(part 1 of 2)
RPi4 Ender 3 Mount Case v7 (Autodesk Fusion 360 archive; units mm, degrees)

design "RPi4 Ender 3 Mount Case" references "40X40 Extrusion 8 slot v2", "RPi_4_dummy_v2"
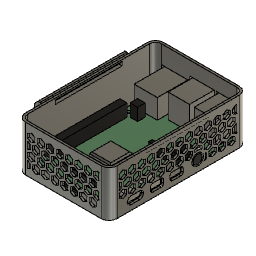
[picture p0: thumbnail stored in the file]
parameter "inner_width" = 60
parameter "inner_length" = 92
parameter "inner_height" = 30
parameter "wall_thickness" = 1.5
parameter "tolerance" = 0.2
parameter "cover_height" = 2
parameter "hole_tolerance" = 1
sketch "Sketch1" plane through (0, 0, 0) normal (0, 0, 1) x axis (1, 0, 0)
  line L1 (60, 0) -> (0, 0)
  line L2 (60, -92) -> (60, 0)
  line L3 (0, -92) -> (60, -92)
  line L4 (0, 0) -> (0, -92)
  point P1 (0, 0)
  point P2 (0, 0)
  point P3 (60, 0)
  point P5 (0, -92)
  horizontal L1
  vertical L2
  horizontal L3
  vertical L4
  coincident P1 P2
  dimension "d6" distance P2 P3 = 60 (= "inner_width")
  dimension "d7" distance P2 P5 = 92 (= "inner_length")
extrude "Extrude1" new body sketch "Sketch1" along normal blind 30 (= "inner_height")
fillet "Fillet1" radius 4
shell "Shell1" outerThickness 1.5 (= "wall_thickness")
sketch "Sketch2" plane through (0, 0, 0) normal (1, 0, 0) x axis (0, 1, 0)
  line L1 (-4, 30) -> (-4, 0)
  line L2 (-88, 30) -> (-4, 30)
  line L3 (-88, 0) -> (-88, 30)
  line L4 (-4, 0) -> (-88, 0)
  line L5 (-23, 28.5) -> (-69, 28.5)
  line L6 (-23, 26.25) -> (-23, 28.5)
  line L7 (-69, 26.25) -> (-23, 26.25)
  line L8 (-69, 28.5) -> (-69, 26.25)
  line L9 (-46, 30) -> (-46, 28.5)
  point P10 (-46, 28.5)
  point P11 (-46, 30)
  point P8 (-23, 26.25)
  point P9 (-69, 26.25)
  point P6 (-69, 28.5)
  horizontal L5
  vertical L6
  horizontal L7
  vertical L8
  midpoint L5 P10
  perpendicular L5 L9
  midpoint L2 P11
  dimension "d32" distance P8 P9 = 46 (= "inner_length / 2")
  dimension "d33" distance P6 P9 = 2.25 (= "wall_thickness * 1.5")
  dimension "d34" distance P10 P11 = 1.5 (= "wall_thickness")
extrude "Extrude2" cut sketch "Sketch2" profile of L5 L6 L7 L8 no distance stored taper -45
work_plane "WorkPlane1"
mirror "Mirror1" mirrorStitchTolerance 0.1
sketch "Sketch1" plane through (0, 0, 30) normal (0, 0, 1) x axis (-1, 0, 0)
  line L1 (-56, 0) -> (-4, 0)
  line L2 (-60, 88) -> (-60, 4)
  line L3 (-4, 92) -> (-56, 92)
  line L4 (0, 4) -> (0, 88)
  line L5 (-61.5, 4) -> (-61.5, 88)
  line L6 (-4, -1.5) -> (-56, -1.5)
  line L7 (1.5, 88) -> (1.5, 4)
  line L8 (-56, 93.5) -> (-4, 93.5)
  arc A1 centre (-4, 4) radius 4 clockwise from (0, 4) to (-4, 0)
  arc A2 centre (-56, 4) radius 4 clockwise from (-56, 0) to (-60, 4)
  arc A3 centre (-56, 88) radius 4 clockwise from (-60, 88) to (-56, 92)
  arc A4 centre (-4, 88) radius 4 clockwise from (-4, 92) to (0, 88)
  arc A5 centre (-56, 88) radius 5.5 clockwise from (-61.5, 88) to (-56, 93.5)
  arc A6 centre (-56, 4) radius 5.5 clockwise from (-56, -1.5) to (-61.5, 4)
  arc A7 centre (-4, 4) radius 5.5 clockwise from (1.5, 4) to (-4, -1.5)
  arc A8 centre (-4, 88) radius 5.5 clockwise from (-4, 93.5) to (1.5, 88)
extrude "Extrude1" new body sketch "Sketch1" along normal blind 2 (= "cover_height")
sketch "Sketch2" plane through (0, 0, 30) normal (0, 0, -1) x axis (1, 0, 0)
  line L1 (4, 93.5) -> (56, 93.5)
  line L2 (-1.5, 4) -> (-1.5, 88)
  line L3 (56, -1.5) -> (4, -1.5)
  line L4 (61.5, 88) -> (61.5, 4)
  line L5 (4, 91.8) -> (56, 91.8)
  line L6 (0.2, 4) -> (0.2, 88)
  line L7 (56, 0.2) -> (4, 0.2)
  line L8 (59.8, 88) -> (59.8, 4)
  arc A1 centre (4, 88) radius 5.5 clockwise from (-1.5, 88) to (4, 93.5)
  arc A2 centre (4, 4) radius 5.5 clockwise from (4, -1.5) to (-1.5, 4)
  arc A3 centre (56, 4) radius 5.5 clockwise from (61.5, 4) to (56, -1.5)
  arc A4 centre (56, 88) radius 5.5 clockwise from (56, 93.5) to (61.5, 88)
  arc A5 centre (4, 88) radius 3.8 clockwise from (0.2, 88) to (4, 91.8)
  arc A6 centre (4, 4) radius 3.8 clockwise from (4, 0.2) to (0.2, 4)
  arc A7 centre (56, 4) radius 3.8 clockwise from (59.8, 4) to (56, 0.2)
  arc A8 centre (56, 88) radius 3.8 clockwise from (56, 91.8) to (59.8, 88)
extrude "Extrude2" add sketch "Sketch2" profile of A8 L8 A7 A6 L6 L7 A5 L5 along normal blind 4.5 (= "wall_thickness * 3")
shell "Shell1" innerThickness 1.5 (= "wall_thickness")
sketch "Sketch3" plane through (0.2, 0, 0) normal (-1, 0, 0) x axis (0, -1, 0)
  line L1 (4, 30) -> (88, 30)
  line L2 (4, 25.5) -> (4, 30)
  line L3 (88, 25.5) -> (4, 25.5)
  line L4 (88, 30) -> (88, 25.5)
  line L5 (69, 26.25) -> (23, 26.25)
  line L6 (69, 28.5) -> (69, 26.25)
  line L7 (23, 26.25) -> (23, 28.5)
  line L8 (23, 28.5) -> (69, 28.5)
extrude "Extrude3" add sketch "Sketch3" profile of L5 L6 L7 L8 along normal blind 1.5 (= "wall_thickness") taper -45
mirror "Mirror1" mirrorStitchTolerance 0.1
offset_faces "OffsetFaces1" distance 0.5
chamfer "Chamfer1" distance 0.5
external_derived "ExternalDerived1" sketch "Sketch3" bodies "Body1", "Body2", "Power USB C", "Micro HDMI 2", "3.5 mm Audio", "Micro HDMI 1", "USB 2.0", "Display"
position "Position1"
sketch "Sketch1" plane through (0, 0, 0) normal (0, 0, 1) x axis (-1, 0, 0)
  line L1 (-60, 4) -> (-60, 88)
  line L2 (-4, 0) -> (-56, 0)
  line L3 (0, 88) -> (0, 4)
  line L4 (-56, 92) -> (-4, 92)
  arc A1 centre (-56, 88) radius 4 clockwise from (-60, 88) to (-56, 92)
  arc A2 centre (-56, 4) radius 4 clockwise from (-56, 0) to (-60, 4)
  arc A3 centre (-4, 4) radius 4 clockwise from (0, 4) to (-4, 0)
  arc A4 centre (-4, 88) radius 4 clockwise from (-4, 92) to (0, 88)
  circle C1 centre (-55.5, 24.9993) radius 1.35
  circle C2 centre (-6.5, 24.9993) radius 1.35
  circle C3 centre (-6.5, 82.9993) radius 1.35
  circle C4 centre (-55.5, 82.9993) radius 1.35
extrude "Extrude3" add sketch "Sketch1" profile of C1 C2 C3 C4 to an object
offset_faces "OffsetFaces1" distance 1.2
sketch "Sketch2" plane through (0, 1.5, 0) normal (0, 1, 0) x axis (-1, 0, 0)
  line L1 (-4, 30) -> (-4, -1.5)
  line L2 (-56, 30) -> (-4, 30)
  line L3 (-56, -1.5) -> (-56, 30)
  line L4 (-4, -1.5) -> (-56, -1.5)
  line L5 (-42.65, 3) -> (-57.35, 3)
  line L6 (-42.65, 19.5) -> (-42.65, 3)
  line L7 (-57.35, 19.5) -> (-42.65, 19.5)
  line L8 (-57.35, 3) -> (-57.35, 19.5)
  line L9 (-24.65, 3) -> (-39.35, 3)
  line L10 (-24.65, 19.5) -> (-24.65, 3)
  line L11 (-39.35, 19.5) -> (-24.65, 19.5)
  line L12 (-39.35, 3) -> (-39.35, 19.5)
  line L13 (-5.25, 3) -> (-21.25, 3)
  line L14 (-5.25, 16.5) -> (-5.25, 3)
  line L15 (-21.25, 16.5) -> (-5.25, 16.5)
  line L16 (-21.25, 3) -> (-21.25, 16.5)
  line L17 (-41.65, 2) -> (-58.35, 2)
  line L18 (-41.65, 20.5) -> (-41.65, 2)
  line L19 (-58.35, 20.5) -> (-41.65, 20.5)
  line L20 (-58.35, 2) -> (-58.35, 20.5)
  line L21 (-23.65, 2) -> (-40.35, 2)
  line L22 (-23.65, 20.5) -> (-23.65, 2)
  line L23 (-40.35, 20.5) -> (-23.65, 20.5)
  line L24 (-40.35, 2) -> (-40.35, 20.5)
  line L25 (-4.25, 2) -> (-22.25, 2)
  line L26 (-4.25, 17.5) -> (-4.25, 2)
  line L27 (-22.25, 17.5) -> (-4.25, 17.5)
  line L28 (-22.25, 2) -> (-22.25, 17.5)
  dimension "d44" = 1 (= "hole_tolerance")
  dimension "d45" = 1 (= "d44")
  dimension "d46" = 1 (= "d45")
extrude "Extrude5" cut sketch "Sketch2" profile of L1 L3 L19 L20 L18 L17 L23 L22 L24 L21 L28 L27 L26 L25 against normal blind 3 (magnitude of "-wall_thickness * 2")
sketch "Sketch3" plane through (61.5, 0, 0) normal (1, 0, 0) x axis (0, 1, 0)
  line L1 (-88, -1.5) -> (-88, 30)
  line L2 (-4, -1.5) -> (-88, -1.5)
  line L3 (-4, 30) -> (-4, -1.5)
  line L4 (-88, 30) -> (-4, 30)
  line L5 (-70.7993, 4.7) -> (-70.7993, 4.5)
  line L6 (-78.2993, 6.2) -> (-72.2993, 6.2)
  line L7 (-79.7993, 4.5) -> (-79.7993, 4.7)
  line L8 (-72.2993, 3) -> (-78.2993, 3)
  line L9 (-56.9493, 5.8) -> (-56.9493, 3.5)
  line L10 (-63.5493, 6.3) -> (-57.4493, 6.3)
  line L11 (-64.0493, 3.5) -> (-64.0493, 5.8)
  line L12 (-57.4493, 3) -> (-63.5493, 3)
  line L13 (-43.4493, 5.8) -> (-43.4493, 3.5)
  line L14 (-50.0493, 6.3) -> (-43.9493, 6.3)
  line L15 (-50.5493, 3.5) -> (-50.5493, 5.8)
  line L16 (-43.9493, 3) -> (-50.0493, 3)
  line L17 (-80.7993, 4.5) -> (-80.7993, 4.7)
  line L18 (-72.2993, 2) -> (-78.2993, 2)
  line L19 (-69.7993, 4.7) -> (-69.7993, 4.5)
  line L20 (-78.2993, 7.2) -> (-72.2993, 7.2)
  line L21 (-65.0493, 3.5) -> (-65.0493, 5.8)
  line L22 (-57.4493, 2) -> (-63.5493, 2)
  line L23 (-55.9493, 5.8) -> (-55.9493, 3.5)
  line L24 (-63.5493, 7.3) -> (-57.4493, 7.3)
  line L25 (-51.5493, 3.5) -> (-51.5493, 5.8)
  line L26 (-43.9493, 2) -> (-50.0493, 2)
  line L27 (-42.4493, 5.8) -> (-42.4493, 3.5)
  line L28 (-50.0493, 7.3) -> (-43.9493, 7.3)
  arc A1 centre (-72.2993, 4.5) radius 1.5 clockwise from (-70.7993, 4.5) to (-72.2993, 3)
  arc A2 centre (-72.2993, 4.7) radius 1.5 clockwise from (-72.2993, 6.2) to (-70.7993, 4.7)
  arc A3 centre (-78.2993, 4.7) radius 1.5 clockwise from (-79.7993, 4.7) to (-78.2993, 6.2)
  arc A4 centre (-78.2993, 4.5) radius 1.5 clockwise from (-78.2993, 3) to (-79.7993, 4.5)
  arc A5 centre (-57.4493, 3.5) radius 0.5 clockwise from (-56.9493, 3.5) to (-57.4493, 3)
  arc A6 centre (-57.4493, 5.8) radius 0.5 clockwise from (-57.4493, 6.3) to (-56.9493, 5.8)
  arc A7 centre (-63.5493, 5.8) radius 0.5 clockwise from (-64.0493, 5.8) to (-63.5493, 6.3)
  arc A8 centre (-63.5493, 3.5) radius 0.5 clockwise from (-63.5493, 3) to (-64.0493, 3.5)
  arc A9 centre (-43.9493, 3.5) radius 0.5 clockwise from (-43.4493, 3.5) to (-43.9493, 3)
  arc A10 centre (-43.9493, 5.8) radius 0.5 clockwise from (-43.9493, 6.3) to (-43.4493, 5.8)
  arc A11 centre (-50.0493, 5.8) radius 0.5 clockwise from (-50.5493, 5.8) to (-50.0493, 6.3)
  arc A12 centre (-50.0493, 3.5) radius 0.5 clockwise from (-50.0493, 3) to (-50.5493, 3.5)
  circle C1 centre (-32.4993, 6) radius 3
  arc A13 centre (-78.2993, 4.5) radius 2.5 clockwise from (-78.2993, 2) to (-80.7993, 4.5)
  arc A14 centre (-72.2993, 4.5) radius 2.5 clockwise from (-69.7993, 4.5) to (-72.2993, 2)
  arc A15 centre (-72.2993, 4.7) radius 2.5 clockwise from (-72.2993, 7.2) to (-69.7993, 4.7)
  arc A16 centre (-78.2993, 4.7) radius 2.5 clockwise from (-80.7993, 4.7) to (-78.2993, 7.2)
  arc A17 centre (-63.5493, 3.5) radius 1.5 clockwise from (-63.5493, 2) to (-65.0493, 3.5)
  arc A18 centre (-57.4493, 3.5) radius 1.5 clockwise from (-55.9493, 3.5) to (-57.4493, 2)
  arc A19 centre (-57.4493, 5.8) radius 1.5 clockwise from (-57.4493, 7.3) to (-55.9493, 5.8)
  arc A20 centre (-63.5493, 5.8) radius 1.5 clockwise from (-65.0493, 5.8) to (-63.5493, 7.3)
  arc A21 centre (-50.0493, 3.5) radius 1.5 clockwise from (-50.0493, 2) to (-51.5493, 3.5)
  arc A22 centre (-43.9493, 3.5) radius 1.5 clockwise from (-42.4493, 3.5) to (-43.9493, 2)
  arc A23 centre (-43.9493, 5.8) radius 1.5 clockwise from (-43.9493, 7.3) to (-42.4493, 5.8)
  arc A24 centre (-50.0493, 5.8) radius 1.5 clockwise from (-51.5493, 5.8) to (-50.0493, 7.3)
  circle C2 centre (-32.4993, 6) radius 4
  dimension "d49" = 1 (= "hole_tolerance")
  dimension "d50" = 1 (= "hole_tolerance")
  dimension "d51" = 1 (= "hole_tolerance")
  dimension "d52" = 1 (= "hole_tolerance")
extrude "Extrude6" cut sketch "Sketch3" profile of A16 L20 A15 L19 L18 A14 A13 L17 L24 A20 A19 L23 L22 A18 A17 L21 L28 A23 A24 L27 L26 A22 A21 L25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 against normal blind 3 (magnitude of "-wall_thickness * 2")
sketch "Sketch5" plane through (61.5, 0, 0) normal (1, 0, 0) x axis (0, 1, 0)
  line L1 (-65.0493, 5.8) -> (-65.0493, 3.5)
  line L2 (-57.4493, 7.3) -> (-63.5493, 7.3)
  line L3 (-55.9493, 3.5) -> (-55.9493, 5.8)
  line L4 (-63.5493, 2) -> (-57.4493, 2)
  line L5 (-51.5493, 5.8) -> (-51.5493, 3.5)
  line L6 (-43.9493, 7.3) -> (-50.0493, 7.3)
  line L7 (-42.4493, 3.5) -> (-42.4493, 5.8)
  line L8 (-50.0493, 2) -> (-43.9493, 2)
  line L9 (-80.7993, 4.7) -> (-80.7993, 4.5)
  line L10 (-72.2993, 7.2) -> (-78.2993, 7.2)
  line L11 (-69.7993, 4.5) -> (-69.7993, 4.7)
  line L12 (-78.2993, 2) -> (-72.2993, 2)
  line L13 (-88, -1.5) -> (-88, 30)
  line L14 (-4, -1.5) -> (-88, -1.5)
  line L15 (-4, 30) -> (-4, -1.5)
  line L16 (-88, 30) -> (-4, 30)
  line L17 (-5.5, 0) -> (-86.5, 0)
  line L18 (-5.5, 28.5) -> (-5.5, 0)
  line L19 (-86.5, 28.5) -> (-5.5, 28.5)
  line L20 (-86.5, 0) -> (-86.5, 28.5)
  line L21 (-72.2993, 8.7) -> (-78.2993, 8.7)
  line L22 (-68.2993, 4.5) -> (-68.2993, 4.7)
  line L23 (-78.2993, 0.5) -> (-72.2993, 0.5)
  line L24 (-82.2993, 4.7) -> (-82.2993, 4.5)
  line L25 (-54.4493, 3.5) -> (-54.4493, 5.8)
  line L26 (-57.4493, 8.8) -> (-63.5493, 8.8)
  line L27 (-66.5493, 5.8) -> (-66.5493, 3.5)
  line L28 (-63.5493, 0.5) -> (-57.4493, 0.5)
  line L29 (-40.9493, 3.5) -> (-40.9493, 5.8)
  line L30 (-43.9493, 8.8) -> (-50.0493, 8.8)
  line L31 (-53.0493, 5.8) -> (-53.0493, 3.5)
  line L32 (-50.0493, 0.5) -> (-43.9493, 0.5)
  line L33 (-87.25, 19.6699) -> (-84.75, 18.2265)
  line L34 (-89.75, 18.2265) -> (-87.25, 19.6699)
  line L35 (-89.75, 15.3397) -> (-89.75, 18.2265)
  line L36 (-87.25, 13.8964) -> (-89.75, 15.3397)
  line L37 (-84.75, 15.3397) -> (-87.25, 13.8964)
  line L38 (-84.75, 18.2265) -> (-84.75, 15.3397)
  line L39 (-84, 25.5) -> (-81.5, 24.0566)
  line L40 (-86.5, 24.0566) -> (-84, 25.5)
  line L41 (-86.5, 21.1699) -> (-86.5, 24.0566)
  line L42 (-84, 19.7265) -> (-86.5, 21.1699)
  line L43 (-81.5, 21.1699) -> (-84, 19.7265)
  line L44 (-81.5, 24.0566) -> (-81.5, 21.1699)
  line L45 (-77.5, 25.5) -> (-75, 24.0566)
  line L46 (-80, 24.0566) -> (-77.5, 25.5)
  line L47 (-80, 21.1699) -> (-80, 24.0566)
  line L48 (-77.5, 19.7265) -> (-80, 21.1699)
  line L49 (-75, 21.1699) -> (-77.5, 19.7265)
  line L50 (-75, 24.0566) -> (-75, 21.1699)
  line L51 (-80.75, 19.6699) -> (-78.25, 18.2265)
  line L52 (-83.25, 18.2265) -> (-80.75, 19.6699)
  line L53 (-83.25, 15.3397) -> (-83.25, 18.2265)
  line L54 (-80.75, 13.8964) -> (-83.25, 15.3397)
  line L55 (-78.25, 18.2265) -> (-78.25, 15.3397)
  line L56 (-78.25, 15.3397) -> (-80.75, 13.8964)
  line L57 (-71, 25.5) -> (-68.5, 24.0566)
  line L58 (-73.5, 24.0566) -> (-71, 25.5)
  line L59 (-73.5, 21.1699) -> (-73.5, 24.0566)
  line L60 (-71, 19.7265) -> (-73.5, 21.1699)
  line L61 (-68.5, 21.1699) -> (-71, 19.7265)
  line L62 (-68.5, 24.0566) -> (-68.5, 21.1699)
  line L63 (-74.25, 19.6699) -> (-71.75, 18.2265)
  line L64 (-76.75, 18.2265) -> (-74.25, 19.6699)
  line L65 (-76.75, 15.3397) -> (-76.75, 18.2265)
  line L66 (-74.25, 13.8964) -> (-76.75, 15.3397)
  line L67 (-71.75, 18.2265) -> (-71.75, 15.3397)
  line L68 (-71.75, 15.3397) -> (-74.25, 13.8964)
  line L69 (-64.5, 25.5) -> (-62, 24.0566)
  line L70 (-67, 24.0566) -> (-64.5, 25.5)
  line L71 (-67, 21.1699) -> (-67, 24.0566)
  line L72 (-64.5, 19.7265) -> (-67, 21.1699)
  line L73 (-62, 21.1699) -> (-64.5, 19.7265)
  line L74 (-62, 24.0566) -> (-62, 21.1699)
  line L75 (-67.75, 19.6699) -> (-65.25, 18.2265)
  line L76 (-70.25, 18.2265) -> (-67.75, 19.6699)
  line L77 (-70.25, 15.3397) -> (-70.25, 18.2265)
  line L78 (-67.75, 13.8964) -> (-70.25, 15.3397)
  line L79 (-65.25, 18.2265) -> (-65.25, 15.3397)
  line L80 (-65.25, 15.3397) -> (-67.75, 13.8964)
  line L81 (-58, 25.5) -> (-55.5, 24.0566)
  line L82 (-60.5, 24.0566) -> (-58, 25.5)
  line L83 (-60.5, 21.1699) -> (-60.5, 24.0566)
  line L84 (-58, 19.7265) -> (-60.5, 21.1699)
  line L85 (-55.5, 21.1699) -> (-58, 19.7265)
  line L86 (-55.5, 24.0566) -> (-55.5, 21.1699)
  line L87 (-61.25, 19.6699) -> (-58.75, 18.2265)
  line L88 (-63.75, 18.2265) -> (-61.25, 19.6699)
  line L89 (-63.75, 15.3397) -> (-63.75, 18.2265)
  line L90 (-61.25, 13.8964) -> (-63.75, 15.3397)
  line L91 (-58.75, 18.2265) -> (-58.75, 15.3397)
  line L92 (-58.75, 15.3397) -> (-61.25, 13.8964)
  line L93 (-51.5, 25.5) -> (-49, 24.0566)
  line L94 (-54, 24.0566) -> (-51.5, 25.5)
  line L95 (-54, 21.1699) -> (-54, 24.0566)
  line L96 (-51.5, 19.7265) -> (-54, 21.1699)
  line L97 (-49, 21.1699) -> (-51.5, 19.7265)
  line L98 (-49, 24.0566) -> (-49, 21.1699)
  line L99 (-54.75, 19.6699) -> (-52.25, 18.2265)
  line L100 (-57.25, 18.2265) -> (-54.75, 19.6699)
  line L101 (-57.25, 15.3397) -> (-57.25, 18.2265)
  line L102 (-54.75, 13.8964) -> (-57.25, 15.3397)
  line L103 (-52.25, 18.2265) -> (-52.25, 15.3397)
  line L104 (-52.25, 15.3397) -> (-54.75, 13.8964)
  line L105 (-45, 25.5) -> (-42.5, 24.0566)
  line L106 (-47.5, 24.0566) -> (-45, 25.5)
  line L107 (-47.5, 21.1699) -> (-47.5, 24.0566)
  line L108 (-45, 19.7265) -> (-47.5, 21.1699)
  line L109 (-42.5, 21.1699) -> (-45, 19.7265)
  line L110 (-42.5, 24.0566) -> (-42.5, 21.1699)
  line L111 (-48.25, 19.6699) -> (-45.75, 18.2265)
  line L112 (-50.75, 18.2265) -> (-48.25, 19.6699)
  line L113 (-50.75, 15.3397) -> (-50.75, 18.2265)
  line L114 (-48.25, 13.8964) -> (-50.75, 15.3397)
  line L115 (-45.75, 18.2265) -> (-45.75, 15.3397)
  line L116 (-45.75, 15.3397) -> (-48.25, 13.8964)
  line L117 (-38.5, 25.5) -> (-36, 24.0566)
  line L118 (-41, 24.0566) -> (-38.5, 25.5)
  line L119 (-41, 21.1699) -> (-41, 24.0566)
  line L120 (-38.5, 19.7265) -> (-41, 21.1699)
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  point P90 (-87.25, 16.7831)
  point P97 (-84, 22.6132)
  point P85 (-87.25, 19.6699)
  point P94 (-86.5, 21.1699)
  point P92 (-84, 25.5)
  vertical L38
  vertical L44
  collinear L20 L41
  dimension "d81" = 1.5 (= "wall_thickness")
  dimension "d84" = 1.5 (= "wall_thickness")
  dimension "d85" distance P90 L38 = 2.5
  dimension "d86" distance P97 L44 = 2.5
  dimension "d87" distance P85 P94 = 1.5 (= "wall_thickness")
  dimension "d88" distance L20 P85 = 0.75 (= "wall_thickness / 2")
  dimension "d95" distance L19 P92 = 3
  dimension "d91" R-Pattern1-uDistance = 6.5
  dimension "d92" R-Pattern1-vDistance = -11.5
extrude "Extrude9" cut sketch "Sketch5" no distance stored
sketch "Sketch6" plane through (0, -93.5, 0) normal (0, -1, 0) x axis (1, 0, 0)
  line L1 (56, 30) -> (56, -1.5)
  line L2 (4, 30) -> (56, 30)
  line L3 (4, -1.5) -> (4, 30)
  line L4 (56, -1.5) -> (4, -1.5)
  line L5 (54.5, 0) -> (5.5, 0)
  line L6 (54.5, 28.5) -> (54.5, 0)
  line L7 (5.5, 28.5) -> (54.5, 28.5)
  line L8 (5.5, 0) -> (5.5, 28.5)
  line L9 (8, 25.5) -> (10.5, 24.0566)
  line L10 (5.5, 24.0566) -> (8, 25.5)
  line L11 (5.5, 21.1699) -> (5.5, 24.0566)
  line L12 (8, 19.7265) -> (5.5, 21.1699)
  line L13 (10.5, 21.1699) -> (8, 19.7265)
  line L14 (10.5, 24.0566) -> (10.5, 21.1699)
  line L15 (4.75, 19.6699) -> (7.25, 18.2265)
  line L16 (2.25, 18.2265) -> (4.75, 19.6699)
  line L17 (2.25, 15.3397) -> (2.25, 18.2265)
  line L18 (4.75, 13.8964) -> (2.25, 15.3397)
  line L19 (7.25, 15.3397) -> (4.75, 13.8964)
  line L20 (7.25, 18.2265) -> (7.25, 15.3397)
  line L21 (14.5, 25.5) -> (17, 24.0566)
  line L22 (12, 24.0566) -> (14.5, 25.5)
  line L23 (12, 21.1699) -> (12, 24.0566)
  line L24 (14.5, 19.7265) -> (12, 21.1699)
  line L25 (17, 21.1699) -> (14.5, 19.7265)
  line L26 (17, 24.0566) -> (17, 21.1699)
  line L27 (11.25, 19.6699) -> (13.75, 18.2265)
  line L28 (8.75, 18.2265) -> (11.25, 19.6699)
  line L29 (8.75, 15.3397) -> (8.75, 18.2265)
  line L30 (11.25, 13.8964) -> (8.75, 15.3397)
  line L31 (13.75, 18.2265) -> (13.75, 15.3397)
  line L32 (13.75, 15.3397) -> (11.25, 13.8964)
  line L33 (21, 25.5) -> (23.5, 24.0566)
  line L34 (18.5, 24.0566) -> (21, 25.5)
  line L35 (18.5, 21.1699) -> (18.5, 24.0566)
  line L36 (21, 19.7265) -> (18.5, 21.1699)
  line L37 (23.5, 21.1699) -> (21, 19.7265)
  line L38 (23.5, 24.0566) -> (23.5, 21.1699)
  line L39 (17.75, 19.6699) -> (20.25, 18.2265)
  line L40 (15.25, 18.2265) -> (17.75, 19.6699)
  line L41 (15.25, 15.3397) -> (15.25, 18.2265)
  line L42 (17.75, 13.8964) -> (15.25, 15.3397)
  line L43 (20.25, 18.2265) -> (20.25, 15.3397)
  line L44 (20.25, 15.3397) -> (17.75, 13.8964)
  line L45 (27.5, 25.5) -> (30, 24.0566)
  line L46 (25, 24.0566) -> (27.5, 25.5)
  line L47 (25, 21.1699) -> (25, 24.0566)
  line L48 (27.5, 19.7265) -> (25, 21.1699)
  line L49 (30, 21.1699) -> (27.5, 19.7265)
  line L50 (30, 24.0566) -> (30, 21.1699)
  line L51 (24.25, 19.6699) -> (26.75, 18.2265)
  line L52 (21.75, 18.2265) -> (24.25, 19.6699)
  line L53 (21.75, 15.3397) -> (21.75, 18.2265)
  line L54 (24.25, 13.8964) -> (21.75, 15.3397)
  line L55 (26.75, 18.2265) -> (26.75, 15.3397)
  line L56 (26.75, 15.3397) -> (24.25, 13.8964)
  line L57 (34, 25.5) -> (36.5, 24.0566)
  line L58 (31.5, 24.0566) -> (34, 25.5)
  line L59 (31.5, 21.1699) -> (31.5, 24.0566)
  line L60 (34, 19.7265) -> (31.5, 21.1699)
  line L61 (36.5, 21.1699) -> (34, 19.7265)
  line L62 (36.5, 24.0566) -> (36.5, 21.1699)
  line L63 (30.75, 19.6699) -> (33.25, 18.2265)
  line L64 (28.25, 18.2265) -> (30.75, 19.6699)
  line L65 (28.25, 15.3397) -> (28.25, 18.2265)
  line L66 (30.75, 13.8964) -> (28.25, 15.3397)
  line L67 (33.25, 18.2265) -> (33.25, 15.3397)
  line L68 (33.25, 15.3397) -> (30.75, 13.8964)
  line L69 (40.5, 25.5) -> (43, 24.0566)
  line L70 (38, 24.0566) -> (40.5, 25.5)
  line L71 (38, 21.1699) -> (38, 24.0566)
  line L72 (40.5, 19.7265) -> (38, 21.1699)
  line L73 (43, 21.1699) -> (40.5, 19.7265)
  line L74 (43, 24.0566) -> (43, 21.1699)
  line L75 (37.25, 19.6699) -> (39.75, 18.2265)
  line L76 (34.75, 18.2265) -> (37.25, 19.6699)
  line L77 (34.75, 15.3397) -> (34.75, 18.2265)
  line L78 (37.25, 13.8964) -> (34.75, 15.3397)
  line L79 (39.75, 18.2265) -> (39.75, 15.3397)
  line L80 (39.75, 15.3397) -> (37.25, 13.8964)
  line L81 (47, 25.5) -> (49.5, 24.0566)
  line L82 (44.5, 24.0566) -> (47, 25.5)
  line L83 (44.5, 21.1699) -> (44.5, 24.0566)
  line L84 (47, 19.7265) -> (44.5, 21.1699)
  line L85 (49.5, 21.1699) -> (47, 19.7265)
  line L86 (49.5, 24.0566) -> (49.5, 21.1699)
  line L87 (43.75, 19.6699) -> (46.25, 18.2265)
  line L88 (41.25, 18.2265) -> (43.75, 19.6699)
  line L89 (41.25, 15.3397) -> (41.25, 18.2265)
  line L90 (43.75, 13.8964) -> (41.25, 15.3397)
  line L91 (46.25, 18.2265) -> (46.25, 15.3397)
  line L92 (46.25, 15.3397) -> (43.75, 13.8964)
  line L93 (53.5, 25.5) -> (56, 24.0566)
  line L94 (51, 24.0566) -> (53.5, 25.5)
  line L95 (51, 21.1699) -> (51, 24.0566)
  line L96 (53.5, 19.7265) -> (51, 21.1699)
  line L97 (56, 21.1699) -> (53.5, 19.7265)
  line L98 (56, 24.0566) -> (56, 21.1699)
  line L99 (50.25, 19.6699) -> (52.75, 18.2265)
  line L100 (47.75, 18.2265) -> (50.25, 19.6699)
  line L101 (47.75, 15.3397) -> (47.75, 18.2265)
  line L102 (50.25, 13.8964) -> (47.75, 15.3397)
  line L103 (52.75, 18.2265) -> (52.75, 15.3397)
  line L104 (52.75, 15.3397) -> (50.25, 13.8964)
  line L105 (8, 14) -> (10.5, 12.5566)
  line L106 (5.5, 12.5566) -> (8, 14)
  line L107 (5.5, 9.6699) -> (5.5, 12.5566)
  line L108 (8, 8.2265) -> (5.5, 9.6699)
  line L109 (10.5, 9.6699) -> (8, 8.2265)
  line L110 (10.5, 12.5566) -> (10.5, 9.6699)
  line L111 (4.75, 8.1699) -> (7.25, 6.7265)
  line L112 (2.25, 6.7265) -> (4.75, 8.1699)
  line L113 (2.25, 3.8397) -> (2.25, 6.7265)
  line L114 (4.75, 2.3964) -> (2.25, 3.8397)
  line L115 (7.25, 6.7265) -> (7.25, 3.8397)
  line L116 (7.25, 3.8397) -> (4.75, 2.3964)
  line L117 (14.5, 14) -> (17, 12.5566)
  line L118 (12, 12.5566) -> (14.5, 14)
  line L119 (12, 9.6699) -> (12, 12.5566)
  line L120 (14.5, 8.2265) -> (12, 9.6699)
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  point P16 (8, 22.6132)
  point P11 (8, 25.5)
  point P23 (4.75, 16.7831)
  point P18 (4.75, 19.6699)
  point P13 (5.5, 21.1699)
  vertical L14
  collinear L8 L11
  vertical L20
  dimension "d99" distance P16 L14 = 2.5
  dimension "d100" distance L7 P11 = 3
  dimension "d101" distance P23 L20 = 2.5
  dimension "d102" distance L8 P18 = 0.75 (= "wall_thickness / 2")
  dimension "d103" distance P13 P18 = 1.5 (= "wall_thickness")
  dimension "d106" R-Pattern1-uDistance = 6.5 (= "( 2.5 * 2 ) * 1 mm + wall_thickness")
  dimension "d107" R-Pattern1-vDistance = -11.5 (= "-( ( 2.5 * 4 ) * 1 mm + wall_thickness )")
extrude "Extrude10" cut sketch "Sketch6" no distance stored
sketch "Sketch4" plane through (0, 0, 30.5) normal (0, 0, -1) x axis (1, 0, 0)
  line L1 (4, 90.3) -> (56, 90.3)
  line L2 (1.7, 4) -> (1.7, 88)
  line L3 (56, 1.7) -> (4, 1.7)
  line L4 (58.3, 88) -> (58.3, 4)
  line L5 (4.7, 4.7) -> (4.7, 87.3)
  line L6 (55.3, 4.7) -> (4.7, 4.7)
  line L7 (55.3, 87.3) -> (55.3, 4.7)
  line L8 (4.7, 87.3) -> (55.3, 87.3)
  line L9 (7.2, 87.3) -> (9.7, 85.8566)
  line L10 (4.7, 85.8566) -> (7.2, 87.3)
  line L11 (4.7, 82.9699) -> (4.7, 85.8566)
  line L12 (7.2, 81.5265) -> (4.7, 82.9699)
  line L13 (9.7, 82.9699) -> (7.2, 81.5265)
  line L14 (9.7, 85.8566) -> (9.7, 82.9699)
  line L15 (3.95, 81.4699) -> (6.45, 80.0265)
  line L16 (1.45, 80.0265) -> (3.95, 81.4699)
  line L17 (1.45, 77.1397) -> (1.45, 80.0265)
  line L18 (3.95, 75.6964) -> (1.45, 77.1397)
  line L19 (6.45, 77.1397) -> (3.95, 75.6964)
  line L20 (6.45, 80.0265) -> (6.45, 77.1397)
  line L21 (13.7, 87.3) -> (16.2, 85.8566)
  line L22 (11.2, 85.8566) -> (13.7, 87.3)
  line L23 (11.2, 82.9699) -> (11.2, 85.8566)
  line L24 (13.7, 81.5265) -> (11.2, 82.9699)
  line L25 (16.2, 85.8566) -> (16.2, 82.9699)
  line L26 (16.2, 82.9699) -> (13.7, 81.5265)
  line L27 (12.95, 80.0265) -> (12.95, 77.1397)
  line L28 (10.45, 81.4699) -> (12.95, 80.0265)
  line L29 (7.95, 80.0265) -> (10.45, 81.4699)
  line L30 (7.95, 77.1397) -> (7.95, 80.0265)
  line L31 (12.95, 77.1397) -> (10.45, 75.6964)
  line L32 (10.45, 75.6964) -> (7.95, 77.1397)
  line L33 (20.2, 87.3) -> (22.7, 85.8566)
  line L34 (17.7, 85.8566) -> (20.2, 87.3)
  line L35 (17.7, 82.9699) -> (17.7, 85.8566)
  line L36 (20.2, 81.5265) -> (17.7, 82.9699)
  line L37 (22.7, 85.8566) -> (22.7, 82.9699)
  line L38 (22.7, 82.9699) -> (20.2, 81.5265)
  line L39 (19.45, 80.0265) -> (19.45, 77.1397)
  line L40 (16.95, 81.4699) -> (19.45, 80.0265)
  line L41 (14.45, 80.0265) -> (16.95, 81.4699)
  line L42 (14.45, 77.1397) -> (14.45, 80.0265)
  line L43 (19.45, 77.1397) -> (16.95, 75.6964)
  line L44 (16.95, 75.6964) -> (14.45, 77.1397)
  line L45 (7.2, 75.8) -> (9.7, 74.3566)
  line L46 (4.7, 74.3566) -> (7.2, 75.8)
  line L47 (4.7, 71.4699) -> (4.7, 74.3566)
  line L48 (7.2, 70.0265) -> (4.7, 71.4699)
  line L49 (9.7, 74.3566) -> (9.7, 71.4699)
  line L50 (9.7, 71.4699) -> (7.2, 70.0265)
  line L51 (6.45, 68.5265) -> (6.45, 65.6397)
  line L52 (3.95, 69.9699) -> (6.45, 68.5265)
  line L53 (1.45, 68.5265) -> (3.95, 69.9699)
  line L54 (1.45, 65.6397) -> (1.45, 68.5265)
  line L55 (6.45, 65.6397) -> (3.95, 64.1964)
  line L56 (3.95, 64.1964) -> (1.45, 65.6397)
  line L57 (13.7, 75.8) -> (16.2, 74.3566)
  line L58 (11.2, 74.3566) -> (13.7, 75.8)
  line L59 (11.2, 71.4699) -> (11.2, 74.3566)
  line L60 (13.7, 70.0265) -> (11.2, 71.4699)
  line L61 (16.2, 74.3566) -> (16.2, 71.4699)
  line L62 (16.2, 71.4699) -> (13.7, 70.0265)
  line L63 (12.95, 68.5265) -> (12.95, 65.6397)
  line L64 (10.45, 69.9699) -> (12.95, 68.5265)
  line L65 (7.95, 68.5265) -> (10.45, 69.9699)
  line L66 (7.95, 65.6397) -> (7.95, 68.5265)
  line L67 (12.95, 65.6397) -> (10.45, 64.1964)
  line L68 (10.45, 64.1964) -> (7.95, 65.6397)
  line L69 (20.2, 75.8) -> (22.7, 74.3566)
  line L70 (17.7, 74.3566) -> (20.2, 75.8)
  line L71 (17.7, 71.4699) -> (17.7, 74.3566)
  line L72 (20.2, 70.0265) -> (17.7, 71.4699)
  line L73 (22.7, 74.3566) -> (22.7, 71.4699)
  line L74 (22.7, 71.4699) -> (20.2, 70.0265)
  line L75 (19.45, 68.5265) -> (19.45, 65.6397)
  line L76 (16.95, 69.9699) -> (19.45, 68.5265)
  line L77 (14.45, 68.5265) -> (16.95, 69.9699)
  line L78 (14.45, 65.6397) -> (14.45, 68.5265)
  line L79 (19.45, 65.6397) -> (16.95, 64.1964)
  line L80 (16.95, 64.1964) -> (14.45, 65.6397)
  line L81 (7.2, 64.3) -> (9.7, 62.8566)
  line L82 (4.7, 62.8566) -> (7.2, 64.3)
  line L83 (4.7, 59.9699) -> (4.7, 62.8566)
  line L84 (7.2, 58.5265) -> (4.7, 59.9699)
  line L85 (9.7, 62.8566) -> (9.7, 59.9699)
  line L86 (9.7, 59.9699) -> (7.2, 58.5265)
  line L87 (6.45, 57.0265) -> (6.45, 54.1397)
  line L88 (3.95, 58.4699) -> (6.45, 57.0265)
  line L89 (1.45, 57.0265) -> (3.95, 58.4699)
  line L90 (1.45, 54.1397) -> (1.45, 57.0265)
  line L91 (6.45, 54.1397) -> (3.95, 52.6964)
  line L92 (3.95, 52.6964) -> (1.45, 54.1397)
  line L93 (13.7, 64.3) -> (16.2, 62.8566)
  line L94 (11.2, 62.8566) -> (13.7, 64.3)
  line L95 (11.2, 59.9699) -> (11.2, 62.8566)
  line L96 (13.7, 58.5265) -> (11.2, 59.9699)
  line L97 (16.2, 62.8566) -> (16.2, 59.9699)
  line L98 (16.2, 59.9699) -> (13.7, 58.5265)
  line L99 (12.95, 57.0265) -> (12.95, 54.1397)
  line L100 (10.45, 58.4699) -> (12.95, 57.0265)
  line L101 (7.95, 57.0265) -> (10.45, 58.4699)
  line L102 (7.95, 54.1397) -> (7.95, 57.0265)
  line L103 (12.95, 54.1397) -> (10.45, 52.6964)
  line L104 (10.45, 52.6964) -> (7.95, 54.1397)
  line L105 (20.2, 64.3) -> (22.7, 62.8566)
  line L106 (17.7, 62.8566) -> (20.2, 64.3)
  line L107 (17.7, 59.9699) -> (17.7, 62.8566)
  line L108 (20.2, 58.5265) -> (17.7, 59.9699)
  line L109 (22.7, 62.8566) -> (22.7, 59.9699)
  line L110 (22.7, 59.9699) -> (20.2, 58.5265)
  line L111 (19.45, 57.0265) -> (19.45, 54.1397)
  line L112 (16.95, 58.4699) -> (19.45, 57.0265)
  line L113 (14.45, 57.0265) -> (16.95, 58.4699)
  line L114 (14.45, 54.1397) -> (14.45, 57.0265)
  line L115 (19.45, 54.1397) -> (16.95, 52.6964)
  line L116 (16.95, 52.6964) -> (14.45, 54.1397)
  line L117 (26.7, 87.3) -> (29.2, 85.8566)
  line L118 (24.2, 85.8566) -> (26.7, 87.3)
  line L119 (24.2, 82.9699) -> (24.2, 85.8566)
  line L120 (26.7, 81.5265) -> (24.2, 82.9699)
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  point P19 (7.2, 87.3)
  point P20 (4.7, 85.8566)
  point P24 (7.2, 84.4132)
  point P31 (3.95, 78.5831)
  point P26 (3.95, 81.4699)
  point P21 (4.7, 82.9699)
  vertical L14
  vertical L20
  coincident L8 P19
  coincident L5 P20
  dimension "d110" = -3
  dimension "d111" distance P24 L14 = 2.5
  dimension "d112" distance P31 L20 = 2.5
  dimension "d113" distance L5 P26 = 0.75 (= "wall_thickness / 2")
  dimension "d114" distance P21 P26 = 1.5 (= "wall_thickness")
  dimension "d117" R-Pattern1-uDistance = 6.5 (= "5 mm + wall_thickness")
  dimension "d118" R-Pattern1-vDistance = -11.5 (= "-( 10 mm + wall_thickness )")
extrude "Extrude4" cut sketch "Sketch4" no distance stored
sketch "Sketch7" plane through (0, 1.5, 0) normal (0, 1, 0) x axis (-1, 0, 0)
  line L1 (-56, -1.5) -> (-56, 2)
  line L2 (-4, 30) -> (-4, -1.5)
  line L3 (-56, 30) -> (-4, 30)
  line L4 (-23.65, 20.5) -> (-40.35, 20.5)
  line L5 (-23.65, 2) -> (-23.65, 20.5)
  line L6 (-4.25, 17.5) -> (-22.25, 17.5)
  line L7 (1.5, 30) -> (1.5, -1.5)
  line L8 (17.1332, 14.25) -> (1.5, 14.25)
  line L9 (17.6053, 24.25) -> (1.5, 24.25)
  line L10 (3.3, 26.75) -> (1.5, 26.75)
  line L11 (3.3, 21.75) -> (3.3, 26.75)
  line L12 (1.5, 21.75) -> (3.3, 21.75)
  line L13 (1.5, 26.75) -> (1.5, 21.75)
  line L14 (4.6, 29.75) -> (3.3, 29.75)
  line L15 (7.8, 21.95) -> (7.8, 26.55)
  line L16 (3.3, 18.75) -> (4.6, 18.75)
  line L17 (3.3, 29.75) -> (3.3, 18.75)
  line L18 (4.6, 18.75) -> (4.6, 29.75)
  line L19 (7.8, 21.95) -> (4.6, 18.75)
  line L20 (9.7192, 18.45) -> (7.8, 18.45)
  line L21 (7.8, 26.55) -> (4.6, 29.75)
  line L22 (9.4083, 30.05) -> (7.8, 30.05)
  line L23 (7.8, 1.95) -> (4.6, -1.25)
  line L24 (7.8, 6.55) -> (7.8, 1.95)
  line L25 (7.8, 6.55) -> (4.6, 9.75)
  line L26 (3.3, 9.75) -> (4.6, 9.75)
  line L27 (4.6, -1.25) -> (3.3, -1.25)
  line L28 (3.3, -1.25) -> (3.3, 9.75)
  line L29 (4.6, 9.75) -> (4.6, -1.25)
  line L30 (1.5, 6.75) -> (3.3, 6.75)
  line L31 (1.5, 1.75) -> (1.5, 6.75)
  line L32 (3.3, 6.75) -> (3.3, 1.75)
  line L33 (3.3, 1.75) -> (1.5, 1.75)
  line L34 (-56, 2) -> (-41.65, 2)
  line L35 (-4, -1.5) -> (-56, -1.5)
  line L36 (-56, 20.5) -> (-56, 30)
  line L37 (-41.65, 20.5) -> (-56, 20.5)
  line L38 (-41.65, 2) -> (-41.65, 20.5)
  line L39 (-40.35, 2) -> (-23.65, 2)
  line L40 (-40.35, 20.5) -> (-40.35, 2)
  line L41 (-22.25, 2) -> (-4.25, 2)
  line L42 (-22.25, 17.5) -> (-22.25, 2)
  line L43 (-4.25, 2) -> (-4.25, 17.5)
  point P14 (1.5, 14.25)
  point P16 (1.5, 24.25)
  point P26 (3.3, 24.25)
  point P18 (1.5, 26.75)
  point P41 (1.5, 1.75)
  point P19 (3.3, 26.75)
  point P42 (3.3, 1.75)
  point P20 (3.3, 21.75)
  point P39 (3.3, 6.75)
  point P21 (1.5, 21.75)
  point P40 (1.5, 6.75)
  point P22 (3.3, 29.75)
  point P38 (3.3, -1.25)
  point P25 (3.3, 18.75)
  point P37 (3.3, 9.75)
  point P27 (4.6, 29.75)
  point P33 (4.6, -1.25)
  point P28 (4.6, 18.75)
  point P36 (4.6, 9.75)
  point P29 (7.8, 21.95)
  point P35 (7.8, 6.55)
  point P31 (7.8, 26.55)
  point P34 (7.8, 1.95)
  midpoint L7 P14
  perpendicular L7 L8
  coincident L7 P16
  perpendicular L7 L9
  horizontal L10
  vertical L11
  horizontal L12
  vertical L13
  midpoint P16 L13
  horizontal L14
  vertical L15
  horizontal L16
  vertical L17
  midpoint L11 P26
  midpoint L17 P26
  perpendicular L16 L18
  horizontal L20
  horizontal L22
  symmetric L8 P18 P41
  symmetric L8 P19 P42
  symmetric L8 P20 P39
  symmetric L8 P21 P40
  symmetric L8 P22 P38
  symmetric L8 P25 P37
  symmetric L8 P27 P33
  symmetric L8 P28 P36
  symmetric L8 P29 P35
  symmetric L8 P31 P34
  dimension "d121" distance L8 L9 = 10
  dimension "d122" distance L10 L12 = 5
  dimension "d123" distance P18 P19 = 1.8
  dimension "d125" distance L14 L16 = 11
  dimension "d126" distance L17 L18 = 1.3
  dimension "d127" angle L19 L20 = 45
  dimension "d128" angle L21 L22 = 45
  dimension "d129" distance L15 L17 = 4.5
work_plane "WorkPlane1" sketch "Sketch7"
extrude "Extrude12" cut sketch "Sketch1" profile of C1 C2 C3 C4 to an object
offset_faces "OffsetFaces2" distance 0.1
sketch "Sketch5" plane through (0, 0, 32) normal (0, 0, 1) x axis (-1, 0, 0)
  line L1 (-6.45, 31.1397) -> (-4.7, 30.1294)
  line L2 (-6.45, 34.0265) -> (-6.45, 31.1397)
  line L3 (-4.7, 35.0369) -> (-6.45, 34.0265)
  line L4 (-4.7, 30.1294) -> (-4.7, 35.0369)
  line L5 (-4.7, 81.0369) -> (-6.45, 80.0265)
  line L6 (-4.7, 76.1294) -> (-4.7, 81.0369)
  line L7 (-6.45, 77.1397) -> (-4.7, 76.1294)
  line L8 (-6.45, 80.0265) -> (-6.45, 77.1397)
  line L9 (-48.7, 39.8566) -> (-48.7, 36.9699)
  line L10 (-46.2, 41.3) -> (-48.7, 39.8566)
  line L11 (-43.7, 39.8566) -> (-46.2, 41.3)
  line L12 (-43.7, 36.9699) -> (-43.7, 39.8566)
  line L13 (-46.2, 35.5265) -> (-43.7, 36.9699)
  line L14 (-48.7, 36.9699) -> (-46.2, 35.5265)
  line L15 (-22.7, 74.3566) -> (-22.7, 71.4699)
  line L16 (-20.2, 75.8) -> (-22.7, 74.3566)
  line L17 (-17.7, 74.3566) -> (-20.2, 75.8)
  line L18 (-17.7, 71.4699) -> (-17.7, 74.3566)
  line L19 (-20.2, 70.0265) -> (-17.7, 71.4699)
  line L20 (-22.7, 71.4699) -> (-20.2, 70.0265)
  line L21 (-29.2, 51.3566) -> (-29.2, 48.4699)
  line L22 (-26.7, 52.8) -> (-29.2, 51.3566)
  line L23 (-24.2, 51.3566) -> (-26.7, 52.8)
  line L24 (-24.2, 48.4699) -> (-24.2, 51.3566)
  line L25 (-26.7, 47.0265) -> (-24.2, 48.4699)
  line L26 (-29.2, 48.4699) -> (-26.7, 47.0265)
  line L27 (-45.45, 77.1397) -> (-42.95, 75.6964)
  line L28 (-45.45, 80.0265) -> (-45.45, 77.1397)
  line L29 (-42.95, 81.4699) -> (-45.45, 80.0265)
  line L30 (-40.45, 80.0265) -> (-42.95, 81.4699)
  line L31 (-40.45, 77.1397) -> (-40.45, 80.0265)
  line L32 (-42.95, 75.6964) -> (-40.45, 77.1397)
  line L33 (-38.95, 65.6397) -> (-36.45, 64.1964)
  line L34 (-38.95, 68.5265) -> (-38.95, 65.6397)
  line L35 (-36.45, 69.9699) -> (-38.95, 68.5265)
  line L36 (-33.95, 68.5265) -> (-36.45, 69.9699)
  line L37 (-33.95, 65.6397) -> (-33.95, 68.5265)
  line L38 (-36.45, 64.1964) -> (-33.95, 65.6397)
  line L39 (-51.95, 65.6397) -> (-49.45, 64.1964)
  line L40 (-51.95, 68.5265) -> (-51.95, 65.6397)
  line L41 (-49.45, 69.9699) -> (-51.95, 68.5265)
  line L42 (-46.95, 68.5265) -> (-49.45, 69.9699)
  line L43 (-46.95, 65.6397) -> (-46.95, 68.5265)
  line L44 (-49.45, 64.1964) -> (-46.95, 65.6397)
  line L45 (-48.7, 85.8566) -> (-48.7, 82.9699)
  line L46 (-46.2, 87.3) -> (-48.7, 85.8566)
  line L47 (-43.7, 85.8566) -> (-46.2, 87.3)
  line L48 (-43.7, 82.9699) -> (-43.7, 85.8566)
  line L49 (-46.2, 81.5265) -> (-43.7, 82.9699)
  line L50 (-48.7, 82.9699) -> (-46.2, 81.5265)
  line L51 (-32.45, 42.6397) -> (-29.95, 41.1964)
  line L52 (-32.45, 45.5265) -> (-32.45, 42.6397)
  line L53 (-29.95, 46.9699) -> (-32.45, 45.5265)
  line L54 (-27.45, 45.5265) -> (-29.95, 46.9699)
  line L55 (-27.45, 42.6397) -> (-27.45, 45.5265)
  line L56 (-29.95, 41.1964) -> (-27.45, 42.6397)
  line L57 (-22.7, 39.8566) -> (-22.7, 36.9699)
  line L58 (-20.2, 41.3) -> (-22.7, 39.8566)
  line L59 (-17.7, 39.8566) -> (-20.2, 41.3)
  line L60 (-17.7, 36.9699) -> (-17.7, 39.8566)
  line L61 (-20.2, 35.5265) -> (-17.7, 36.9699)
  line L62 (-22.7, 36.9699) -> (-20.2, 35.5265)
  line L63 (-16.2, 62.8566) -> (-16.2, 59.9699)
  line L64 (-13.7, 64.3) -> (-16.2, 62.8566)
  line L65 (-11.2, 62.8566) -> (-13.7, 64.3)
  line L66 (-11.2, 59.9699) -> (-11.2, 62.8566)
  line L67 (-13.7, 58.5265) -> (-11.2, 59.9699)
  line L68 (-16.2, 59.9699) -> (-13.7, 58.5265)
  line L69 (-29.2, 74.3566) -> (-29.2, 71.4699)
  line L70 (-26.7, 75.8) -> (-29.2, 74.3566)
  line L71 (-24.2, 74.3566) -> (-26.7, 75.8)
  line L72 (-24.2, 71.4699) -> (-24.2, 74.3566)
  line L73 (-26.7, 70.0265) -> (-24.2, 71.4699)
  line L74 (-29.2, 71.4699) -> (-26.7, 70.0265)
  line L75 (-7.2, 87.3) -> (-9.7, 85.8566)
  line L76 (-4.7, 85.8566) -> (-7.2, 87.3)
  line L77 (-4.7, 82.9699) -> (-4.7, 85.8566)
  line L78 (-7.2, 81.5265) -> (-4.7, 82.9699)
  line L79 (-9.7, 82.9699) -> (-7.2, 81.5265)
  line L80 (-9.7, 85.8566) -> (-9.7, 82.9699)
  line L81 (-19.45, 54.1397) -> (-16.95, 52.6964)
  line L82 (-19.45, 57.0265) -> (-19.45, 54.1397)
  line L83 (-16.95, 58.4699) -> (-19.45, 57.0265)
  line L84 (-14.45, 57.0265) -> (-16.95, 58.4699)
  line L85 (-14.45, 54.1397) -> (-14.45, 57.0265)
  line L86 (-16.95, 52.6964) -> (-14.45, 54.1397)
  line L87 (-16.2, 51.3566) -> (-16.2, 48.4699)
  line L88 (-13.7, 52.8) -> (-16.2, 51.3566)
  line L89 (-11.2, 51.3566) -> (-13.7, 52.8)
  line L90 (-11.2, 48.4699) -> (-11.2, 51.3566)
  line L91 (-13.7, 47.0265) -> (-11.2, 48.4699)
  line L92 (-16.2, 48.4699) -> (-13.7, 47.0265)
  line L93 (-9.7, 28.3566) -> (-9.7, 25.4699)
  line L94 (-7.2, 29.8) -> (-9.7, 28.3566)
  line L95 (-4.7, 28.3566) -> (-7.2, 29.8)
  line L96 (-4.7, 25.4699) -> (-4.7, 28.3566)
  line L97 (-7.2, 24.0265) -> (-4.7, 25.4699)
  line L98 (-9.7, 25.4699) -> (-7.2, 24.0265)
  line L99 (-55.2, 39.8566) -> (-55.2, 36.9699)
  line L100 (-52.7, 41.3) -> (-55.2, 39.8566)
  line L101 (-50.2, 39.8566) -> (-52.7, 41.3)
  line L102 (-50.2, 36.9699) -> (-50.2, 39.8566)
  line L103 (-52.7, 35.5265) -> (-50.2, 36.9699)
  line L104 (-55.2, 36.9699) -> (-52.7, 35.5265)
  line L105 (-32.45, 31.1397) -> (-29.95, 29.6964)
  line L106 (-32.45, 34.0265) -> (-32.45, 31.1397)
  line L107 (-29.95, 35.4699) -> (-32.45, 34.0265)
  line L108 (-27.45, 34.0265) -> (-29.95, 35.4699)
  line L109 (-27.45, 31.1397) -> (-27.45, 34.0265)
  line L110 (-29.95, 29.6964) -> (-27.45, 31.1397)
  line L111 (-48.7, 62.8566) -> (-48.7, 59.9699)
  line L112 (-46.2, 64.3) -> (-48.7, 62.8566)
  line L113 (-43.7, 62.8566) -> (-46.2, 64.3)
  line L114 (-43.7, 59.9699) -> (-43.7, 62.8566)
  line L115 (-46.2, 58.5265) -> (-43.7, 59.9699)
  line L116 (-48.7, 59.9699) -> (-46.2, 58.5265)
  line L117 (-45.45, 42.6397) -> (-42.95, 41.1964)
  line L118 (-45.45, 45.5265) -> (-45.45, 42.6397)
  line L119 (-42.95, 46.9699) -> (-45.45, 45.5265)
  line L120 (-40.45, 45.5265) -> (-42.95, 46.9699)
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external_derived "ExternalDerived1" bodies "Body1"
position "Position2"
move "Move1"
move "Move2"
move "Move3"
move "Move4"
sketch "Sketch4" plane through (0, 1.5, 0) normal (0, 1, 0) x axis (-1, 0, 0)
  line L1 (-23.65, 20.5) -> (-40.35, 20.5)
  line L2 (-23.65, 2) -> (-23.65, 20.5)
  line L3 (-4.25, 17.5) -> (-22.25, 17.5)
  line L4 (-4, 30) -> (-4, -1.5)
  line L5 (-56, 30) -> (-4, 30)
  line L6 (-56, -1.5) -> (-56, 2)
  line L7 (2.6902, 26.9504) -> (1.5002, 28.1404)
  line L8 (3.3002, 26.9504) -> (2.6902, 26.9504)
  line L9 (3.3002, 29.3504) -> (3.3002, 26.9504)
  line L10 (5.0102, 29.3504) -> (3.3002, 29.3504)
  line L11 (7.6002, 20.9403) -> (7.6002, 26.7604)
  line L12 (7.6002, 26.7604) -> (5.0102, 29.3504)
  line L13 (5.0102, 18.3504) -> (7.6002, 20.9403)
  line L14 (3.3002, 18.3504) -> (5.0102, 18.3504)
  line L15 (3.3002, 20.7504) -> (3.3002, 18.3504)
  line L16 (2.6902, 20.7504) -> (3.3002, 20.7504)
  line L17 (1.5002, 19.5604) -> (2.6902, 20.7504)
  line L18 (2.6902, 6.9504) -> (1.5002, 8.1404)
  line L19 (3.3002, 6.9504) -> (2.6902, 6.9504)
  line L20 (3.3002, 9.3504) -> (3.3002, 6.9504)
  line L21 (5.0102, 9.3504) -> (3.3002, 9.3504)
  line L22 (7.6002, 6.7604) -> (5.0102, 9.3504)
  line L23 (7.6002, 0.9403) -> (7.6002, 6.7604)
  line L24 (5.0102, -1.6496) -> (7.6002, 0.9403)
  line L25 (3.3002, -1.6496) -> (5.0102, -1.6496)
  line L26 (3.3002, 0.7504) -> (3.3002, -1.6496)
  line L27 (2.6902, 0.7504) -> (3.3002, 0.7504)
  line L28 (1.5002, -0.4396) -> (2.6902, 0.7504)
  line L29 (2.6281, 26.8004) -> (1.3941, 28.0343)
  line L30 (3.4502, 26.8004) -> (2.6281, 26.8004)
  line L31 (3.4502, 29.2004) -> (3.4502, 26.8004)
  line L32 (4.9481, 29.2004) -> (3.4502, 29.2004)
  line L33 (7.4502, 26.6983) -> (4.9481, 29.2004)
  line L34 (7.4502, 21.0025) -> (7.4502, 26.6983)
  line L35 (4.9481, 18.5004) -> (7.4502, 21.0025)
  line L36 (3.4502, 18.5004) -> (4.9481, 18.5004)
  line L37 (3.4502, 20.9004) -> (3.4502, 18.5004)
  line L38 (2.6281, 20.9004) -> (3.4502, 20.9004)
  line L39 (1.3941, 19.6664) -> (2.6281, 20.9004)
  line L40 (2.6281, 6.8004) -> (1.3941, 8.0343)
  line L41 (3.4502, 6.8004) -> (2.6281, 6.8004)
  line L42 (3.4502, 9.2004) -> (3.4502, 6.8004)
  line L43 (4.9481, 9.2004) -> (3.4502, 9.2004)
  line L44 (7.4502, 6.6983) -> (4.9481, 9.2004)
  line L45 (7.4502, 1.0025) -> (7.4502, 6.6983)
  line L46 (4.9481, -1.4996) -> (7.4502, 1.0025)
  line L47 (3.4502, -1.4996) -> (4.9481, -1.4996)
  line L48 (3.4502, 0.9004) -> (3.4502, -1.4996)
  line L49 (2.6281, 0.9004) -> (3.4502, 0.9004)
  line L50 (1.3941, -0.3336) -> (2.6281, 0.9004)
  line L51 (1.5, 30) -> (1.5, -1.5)
  line L52 (1.5, 27.9285) -> (2.6281, 26.8004)
  line L53 (1.5, 19.7723) -> (2.6281, 20.9004)
  line L54 (1.5, 7.9285) -> (2.6281, 6.8004)
  line L55 (1.5, -0.2277) -> (2.6281, 0.9004)
  line L56 (-56, 2) -> (-41.65, 2)
  line L57 (-4, -1.5) -> (-56, -1.5)
  line L58 (-56, 20.5) -> (-56, 30)
  line L59 (-41.65, 20.5) -> (-56, 20.5)
  line L60 (-41.65, 2) -> (-41.65, 20.5)
  line L61 (-40.35, 2) -> (-23.65, 2)
  line L62 (-40.35, 20.5) -> (-40.35, 2)
  line L63 (-22.25, 2) -> (-4.25, 2)
  line L64 (-22.25, 17.5) -> (-22.25, 2)
  line L65 (-4.25, 2) -> (-4.25, 17.5)
  point P58 (1.5, 27.9285)
  point P59 (1.5, 19.7723)
  point P60 (1.5, 7.9285)
  point P61 (1.5, -0.2277)
  coincident L51 P58
  parallel L29 L52
  coincident L51 P59
  perpendicular L52 L53
  coincident L51 P60
  perpendicular L53 L54
  coincident L51 P61
  perpendicular L54 L55
  dimension "d140" = 0.15
  dimension "d141" = 0.15
work_plane "WorkPlane2" sketch "Sketch4"
extrude "Extrude13" sketch "Sketch4" profile of L39 L38 L37 L34 L36 L30 L32 L31 L35 L33 L29 L48 L46 L45 L50 L44 L43 L47 L42 L41 L49 L40 L51 L52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 blind 30 second side blind 30
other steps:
derived_base_feature "Derived Base Feature1" bodies "Body1"
derived_base_feature "Derived Base Feature1" sketch "Sketch3" bodies "Body1", "Body2"
derived_base_feature "Derived Base Feature2" bodies "Power USB C"
derived_base_feature "Derived Base Feature3" bodies "Micro HDMI 2"
derived_base_feature "Derived Base Feature4" bodies "3.5 mm Audio"
derived_base_feature "Derived Base Feature5" bodies "Micro HDMI 1"
derived_base_feature "Derived Base Feature6" bodies "USB 2.0"
derived_base_feature "Derived Base Feature7" bodies "Display"
derived_base_feature "Derived Base Feature8" bodies "Processor"
derived_base_feature "Derived Base Feature9" bodies "Ethernet"
derived_base_feature "Derived Base Feature10" bodies "Kamera"
derived_base_feature "Derived Base Feature11" bodies "GPIO 40"
derived_base_feature "Derived Base Feature12" bodies "USB 3.0"
derived_base_feature "Derived Base Feature13" bodies "PoE"
create_component "CreateComponent1"
create_component "CreateComponent1"
create_component "CreateComponent2"
create_component "CreateComponent2"
create_component "CreateComponent3"
named bodies: "Power USB C", "Micro HDMI 2", "3.5 mm Audio", "Micro HDMI 1", "USB 2.0", "Display", "Processor", "Ethernet", "Kamera", "GPIO 40", "USB 3.0", "PoE", "Body1", "Body2"

design "40X40 Extrusion 8 slot v2"
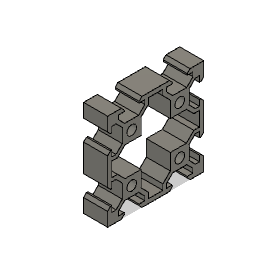
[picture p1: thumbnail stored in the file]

design "RPi_4_dummy_v2"
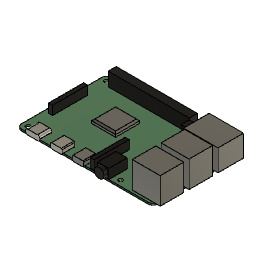
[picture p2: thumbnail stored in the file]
canvas "Ansichtsbereich"
sketch "Skizze4" plane through (0, 0, 0) normal (0, 0, 1) x axis (1, 0, 0)
  line L1 (52.4985, 25) -> (52.4985, -25)
  line L2 (-32.5, -25.0196) -> (-32.5, 24.5)
  line L3 (-29.5, 28) -> (49.4985, 28)
  line L4 (-32.5, 24.5) -> (-32.5, 25)
  line L5 (-29.5, -28) -> (49.4985, -28)
  line L6 (-32.5, -25.0196) -> (-32.5, -25)
  line L7 (29, -24.5) -> (-29, 24.5)
  line L8 (-29, -24.5) -> (29, 24.5)
  line L9 (-29, -24.5) -> (-29, 24.5)
  line L10 (29, -24.5) -> (-29, -24.5)
  line L11 (29, 24.5) -> (29, -24.5)
  line L12 (29, 24.5) -> (-29, 24.5)
  circle C1 centre (29, 24.5) radius 1.35
  circle C2 centre (29, -24.5) radius 1.35
  circle C3 centre (-29, -24.5) radius 1.35
  circle C4 centre (-29, 24.5) radius 1.35
  arc A1 centre (-29.5, 25) radius 3 clockwise from (-32.5, 25) to (-29.5, 28)
  arc A2 centre (-29.5, -25) radius 3 clockwise from (-29.5, -28) to (-32.5, -25)
  arc A3 centre (49.4985, -25) radius 3 clockwise from (52.4985, -25) to (49.4985, -28)
  arc A4 centre (49.4985, 25) radius 3 clockwise from (49.4985, 28) to (52.4985, 25)
  point P6 (-32.5, 28)
  point P4 (52.4985, 25)
  point P20 (52.4985, 25)
  point P10 (-29, 24.5)
  point P23 (-29, 24.5)
  point P8 (29, -24.5)
  point P24 (29, -24.5)
  point P7 (29, 24.5)
  point P25 (29, 24.5)
  point P9 (-29, -24.5)
  point P26 (-29, -24.5)
  point P27 (0, 0)
  point P1 (0, 0)
  point P3 (52.4985, -25)
  point P18 (52.4985, -25)
  point P28 (0, 0)
  point P29 (-29, 24.5)
  point P30 (-29, -24.5)
  point P31 (29, -24.5)
  point P32 (29, 24.5)
  point P33 (-29, 24.5)
  point P5 (-32.5, 24.5)
  parallel L1 L2
  horizontal L3
  vertical L4
  horizontal L5
  vertical L6
  coincident P6 L3
  coincident P6 L4
  tangent L3 A1
  tangent L4 A1
  tangent L5 A2
  tangent L6 A2
  tangent L5 A3
  equal A2 A3
  tangent L3 A4
  equal A2 A4
  equal A1 A2
  equal C2 C3
  equal C3 C4
  equal C1 C4
  coincident P4 P20
  coincident P10 P23
  coincident P8 P24
  coincident P7 P25
  coincident P9 P26
  midpoint L7 P27
  coincident P1 P27
  coincident P3 P18
  midpoint L8 P28
  coincident P1 P28
  vertical L1
  coincident P10 P29
  coincident P9 P30
  coincident P8 P31
  coincident P7 P32
  coincident P10 P33
  horizontal L12
  vertical L11
  tangent L1 A3
  tangent L1 A4
  dimension "d3" distance P4 P5 = 85
  dimension "d6" distance P5 P6 = 3.5
  dimension "d11" diameter C3 = 2.7
  dimension "d17" radius A1 = 3
  dimension "d57" distance P9 P10 = 49
  dimension "d58" distance P7 P10 = 58
  dimension "d61" distance L3 L5 = 56
  dimension "d62" distance L2 P10 = 3.5
  dimension "d63" distance L3 P10 = 3.5
extrude "Extrusion7" new body sketch "Skizze4" profile of L1 L2 L3 L4 L5 C1 C2 C3 C4 A1 A2 A3 A4 along normal blind 1
component_from_bodies "Körper->Berechn3"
